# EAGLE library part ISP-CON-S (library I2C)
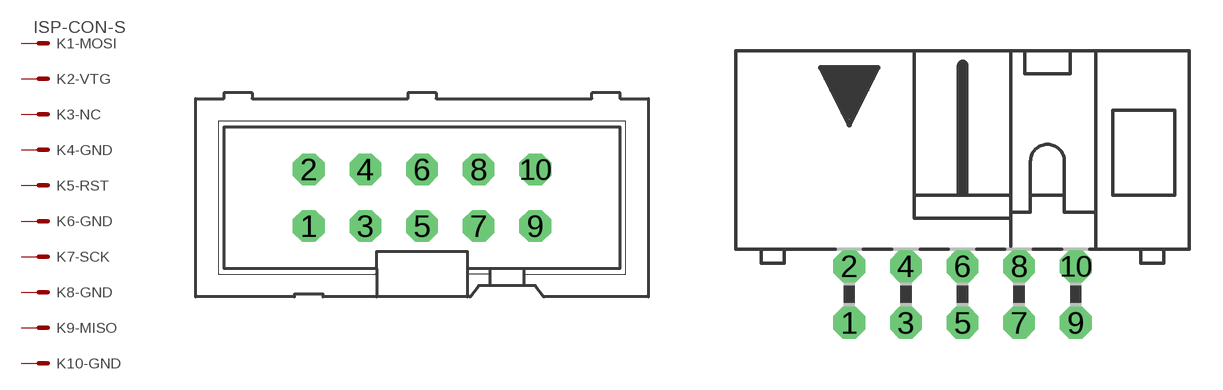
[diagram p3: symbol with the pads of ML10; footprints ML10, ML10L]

Designator prefix K; gates 1-MOSI=MV 2-VTG=M 3-NC=M 4-GND=M 5-RST=M 6-GND=M 7-SCK=M 8-GND=M 9-MISO=M 10-GND=M

## ISP-CON-S  [ML10]
1  1-MOSI:S  pas
2  2-VTG:S  pas
3  3-NC:S  pas
4  4-GND:S  pas
5  5-RST:S  pas
6  6-GND:S  pas
7  7-SCK:S  pas
8  8-GND:S  pas
9  9-MISO:S  pas
10  10-GND:S  pas

## ISP-CON-SL  [ML10L]
Pads as for ML10

## Footprint ML10 (pad centres in mm)
drill 0.914 octagon: 1 -5.08,-1.27; 2 -5.08,1.27; 3 -2.54,-1.27; 4 -2.54,1.27; 5 0,-1.27; 6 0,1.27; 7 2.54,-1.27; 8 2.54,1.27; 9 5.08,-1.27; 10 5.08,1.27

## Footprint ML10L (pad centres in mm)
drill 0.914 octagon: 1 -5.08,-7.62; 2 -5.08,-5.08; 3 -2.54,-7.62; 4 -2.54,-5.08; 5 0,-7.62; 6 0,-5.08; 7 2.54,-7.62; 8 2.54,-5.08; 9 5.08,-7.62; 10 5.08,-5.08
